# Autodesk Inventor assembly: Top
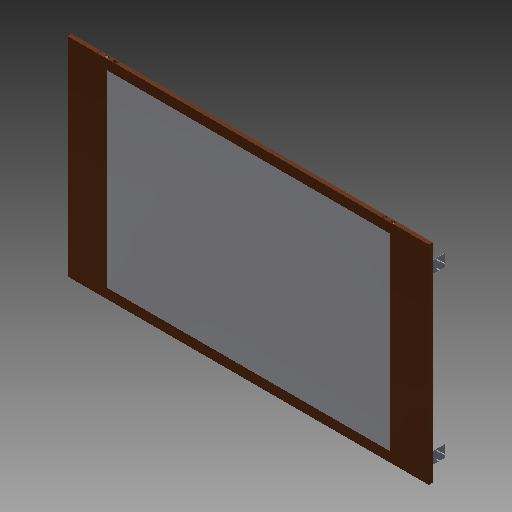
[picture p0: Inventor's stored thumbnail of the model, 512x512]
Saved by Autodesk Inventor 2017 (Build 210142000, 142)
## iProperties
Created: 2017-05
Part Number: Top
Document SubType Name: Assembly
Designer: Savy
Author: Savy
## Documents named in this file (10)
- D:\3D Printer Designs\John Ledden Designs\Infinity Mirror Table\SavanDrawings\Top.iam
- D:\3D Printer Designs\John Ledden Designs\Infinity Mirror Table\SavanDrawings\OneWayAcrylic.ipt
- D:\3D Printer Designs\John Ledden Designs\Infinity Mirror Table\SavanDrawings\TopSidePanel_Long.ipt
- D:\3D Printer Designs\John Ledden Designs\Infinity Mirror Table\SavanDrawings\TopSidePanel_Short.ipt
- D:\3D Printer Designs\John Ledden Designs\Infinity Mirror Table\SavanDrawings\TopCutout_Cover.ipt
- D:\3D Printer Designs\John Ledden Designs\Infinity Mirror Table\SavanDrawings\8_Screw_1inch.ipt
- D:\3D Printer Designs\John Ledden Designs\Infinity Mirror Table\SavanDrawings\17715A430_BRACKET_step.ipt
- D:\3D Printer Designs\John Ledden Designs\Infinity Mirror Table\SavanDrawings\TopGlass.ipt
- D:\3D Printer Designs\John Ledden Designs\Infinity Mirror Table\SavanDrawings\8_Screw_-5inch.ipt
- D:\3D Printer Designs\John Ledden Designs\Infinity Mirror Table\SavanDrawings\TapeStrip.ipt
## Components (36 placed, 36 different names)
1. OneWayAcrylic_1291
2. TopSidePanel_Long_1292
3. TopSidePanel_Short_1293
4. TopSidePanel_Short_1294
5. TopSidePanel_Long_1295
6. TopCutout_Cover_1296
7. 8_Screw_1inch_1297
8. 8_Screw_1inch_1298
9. 8_Screw_1inch_1299
10. 8_Screw_1inch_1300
11. 8_Screw_1inch_1301
12. 8_Screw_1inch_1302
13. 8_Screw_1inch_1303
14. 8_Screw_1inch_1304
15. 17715A430_BRACKET_step_1305
16. 17715A430_BRACKET_step_1306
17. 17715A430_BRACKET_step_1307
18. 17715A430_BRACKET_step_1308
19. TopCutout_Cover_1309
20. TopGlass_1310
21. 8_Screw_-5inch_1311
22. 8_Screw_-5inch_1312
23. 8_Screw_-5inch_1313
24. 8_Screw_-5inch_1314
25. 8_Screw_-5inch_1315
26. 8_Screw_-5inch_1316
27. 8_Screw_-5inch_1317
28. 8_Screw_-5inch_1318
29. 8_Screw_-5inch_1319
30. 8_Screw_-5inch_1320
31. 8_Screw_-5inch_1321
32. 8_Screw_-5inch_1322
33. TapeStrip_1335
34. TapeStrip_1336
35. TapeStrip_1337
36. TapeStrip_1338
